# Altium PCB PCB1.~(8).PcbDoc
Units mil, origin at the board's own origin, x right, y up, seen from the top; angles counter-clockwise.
Board outline 2756 x 2756 mil, 4 copper layers (Top Layer, Internal Plane 1, Internal Plane 2, Bottom Layer), stack 18.2 mil thick; 17 components, 14 nets, 62 pads, 0 vias.
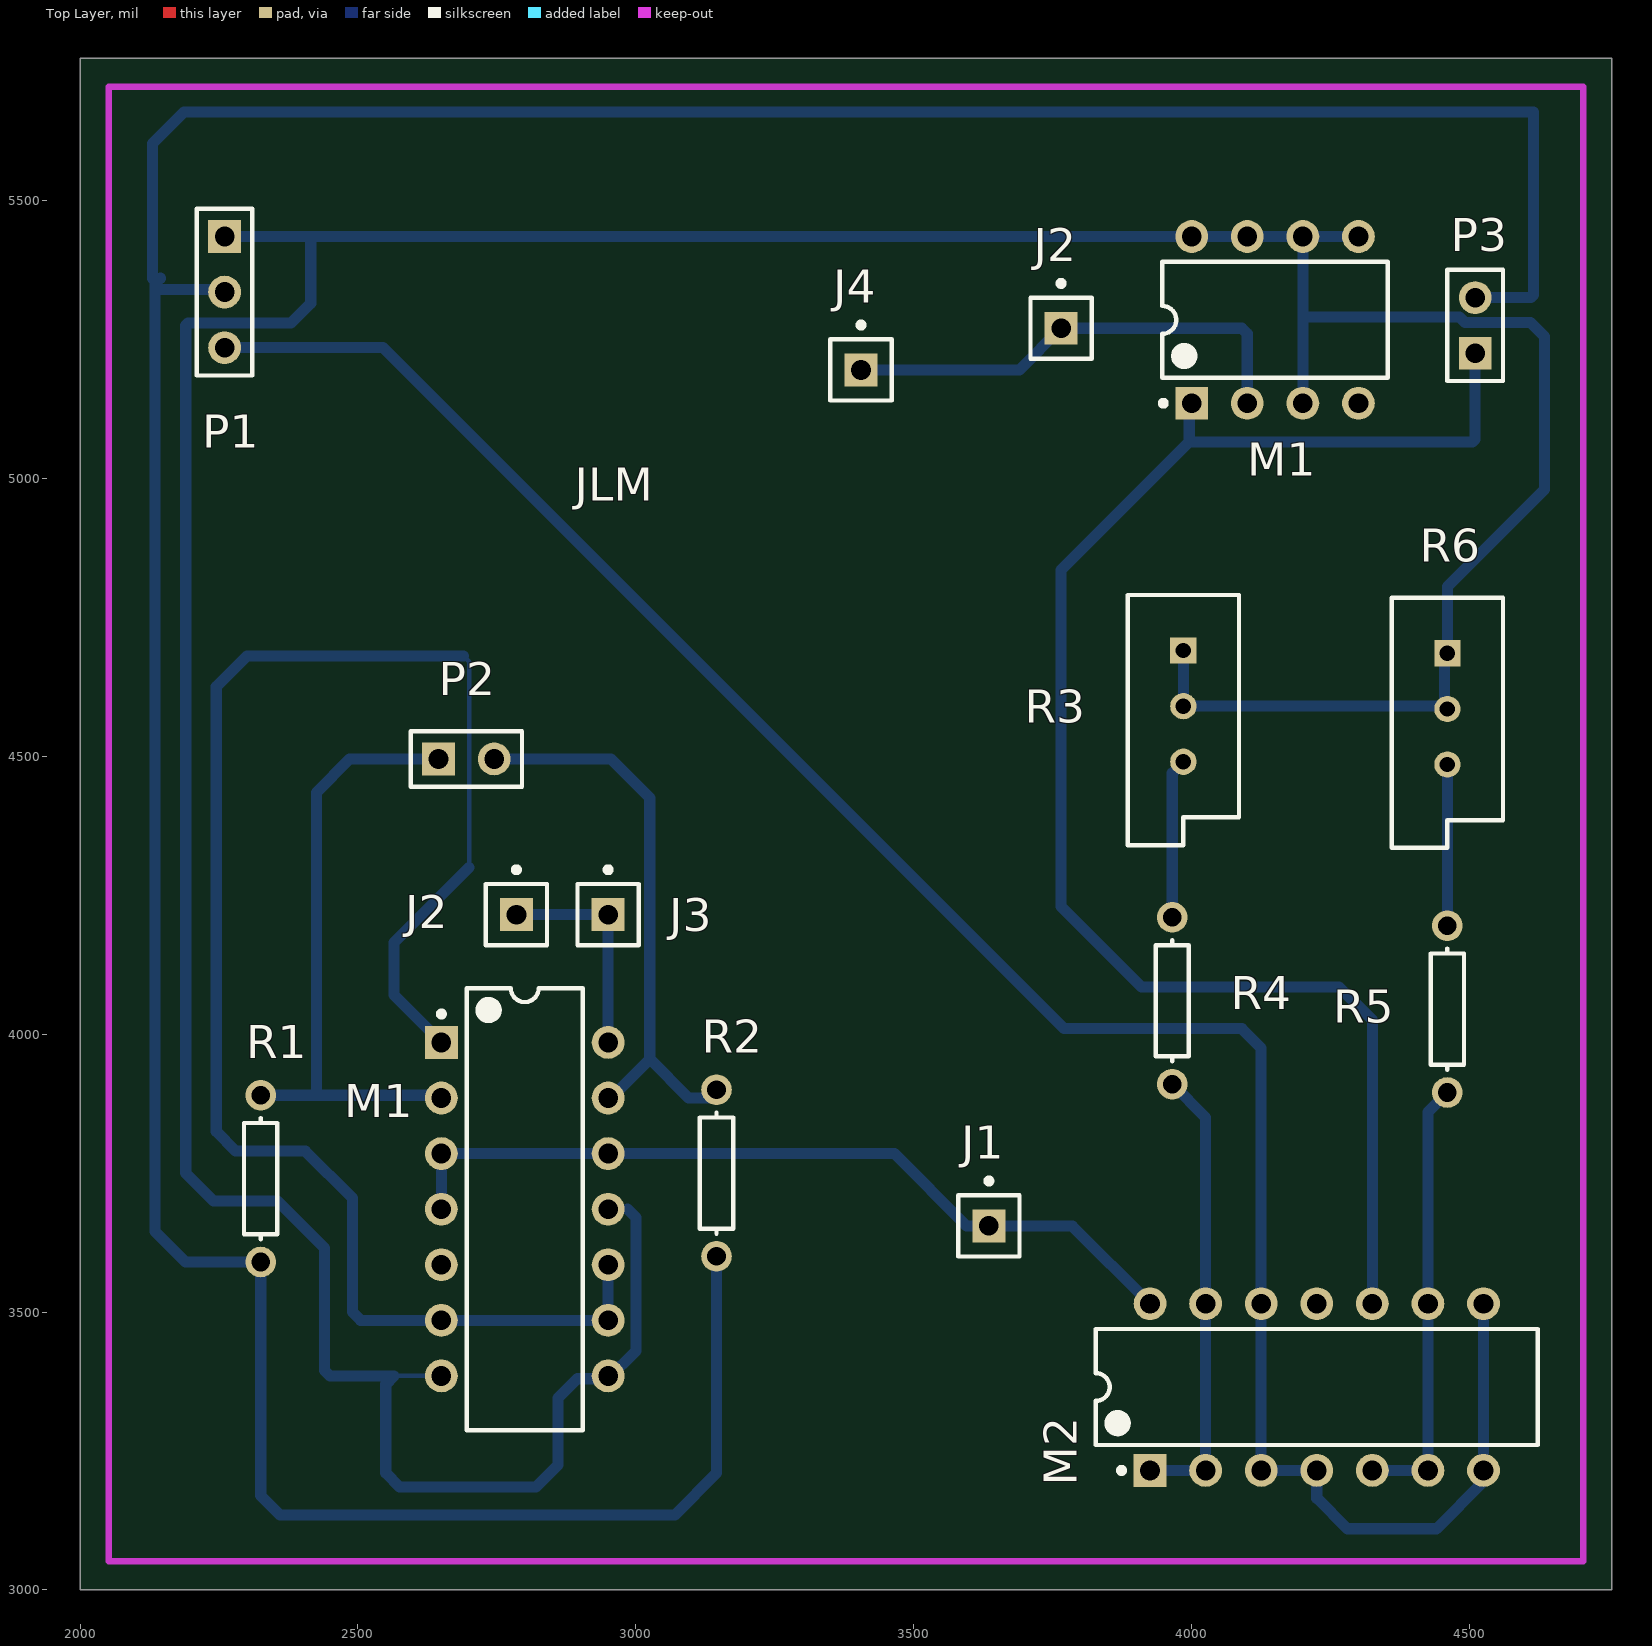
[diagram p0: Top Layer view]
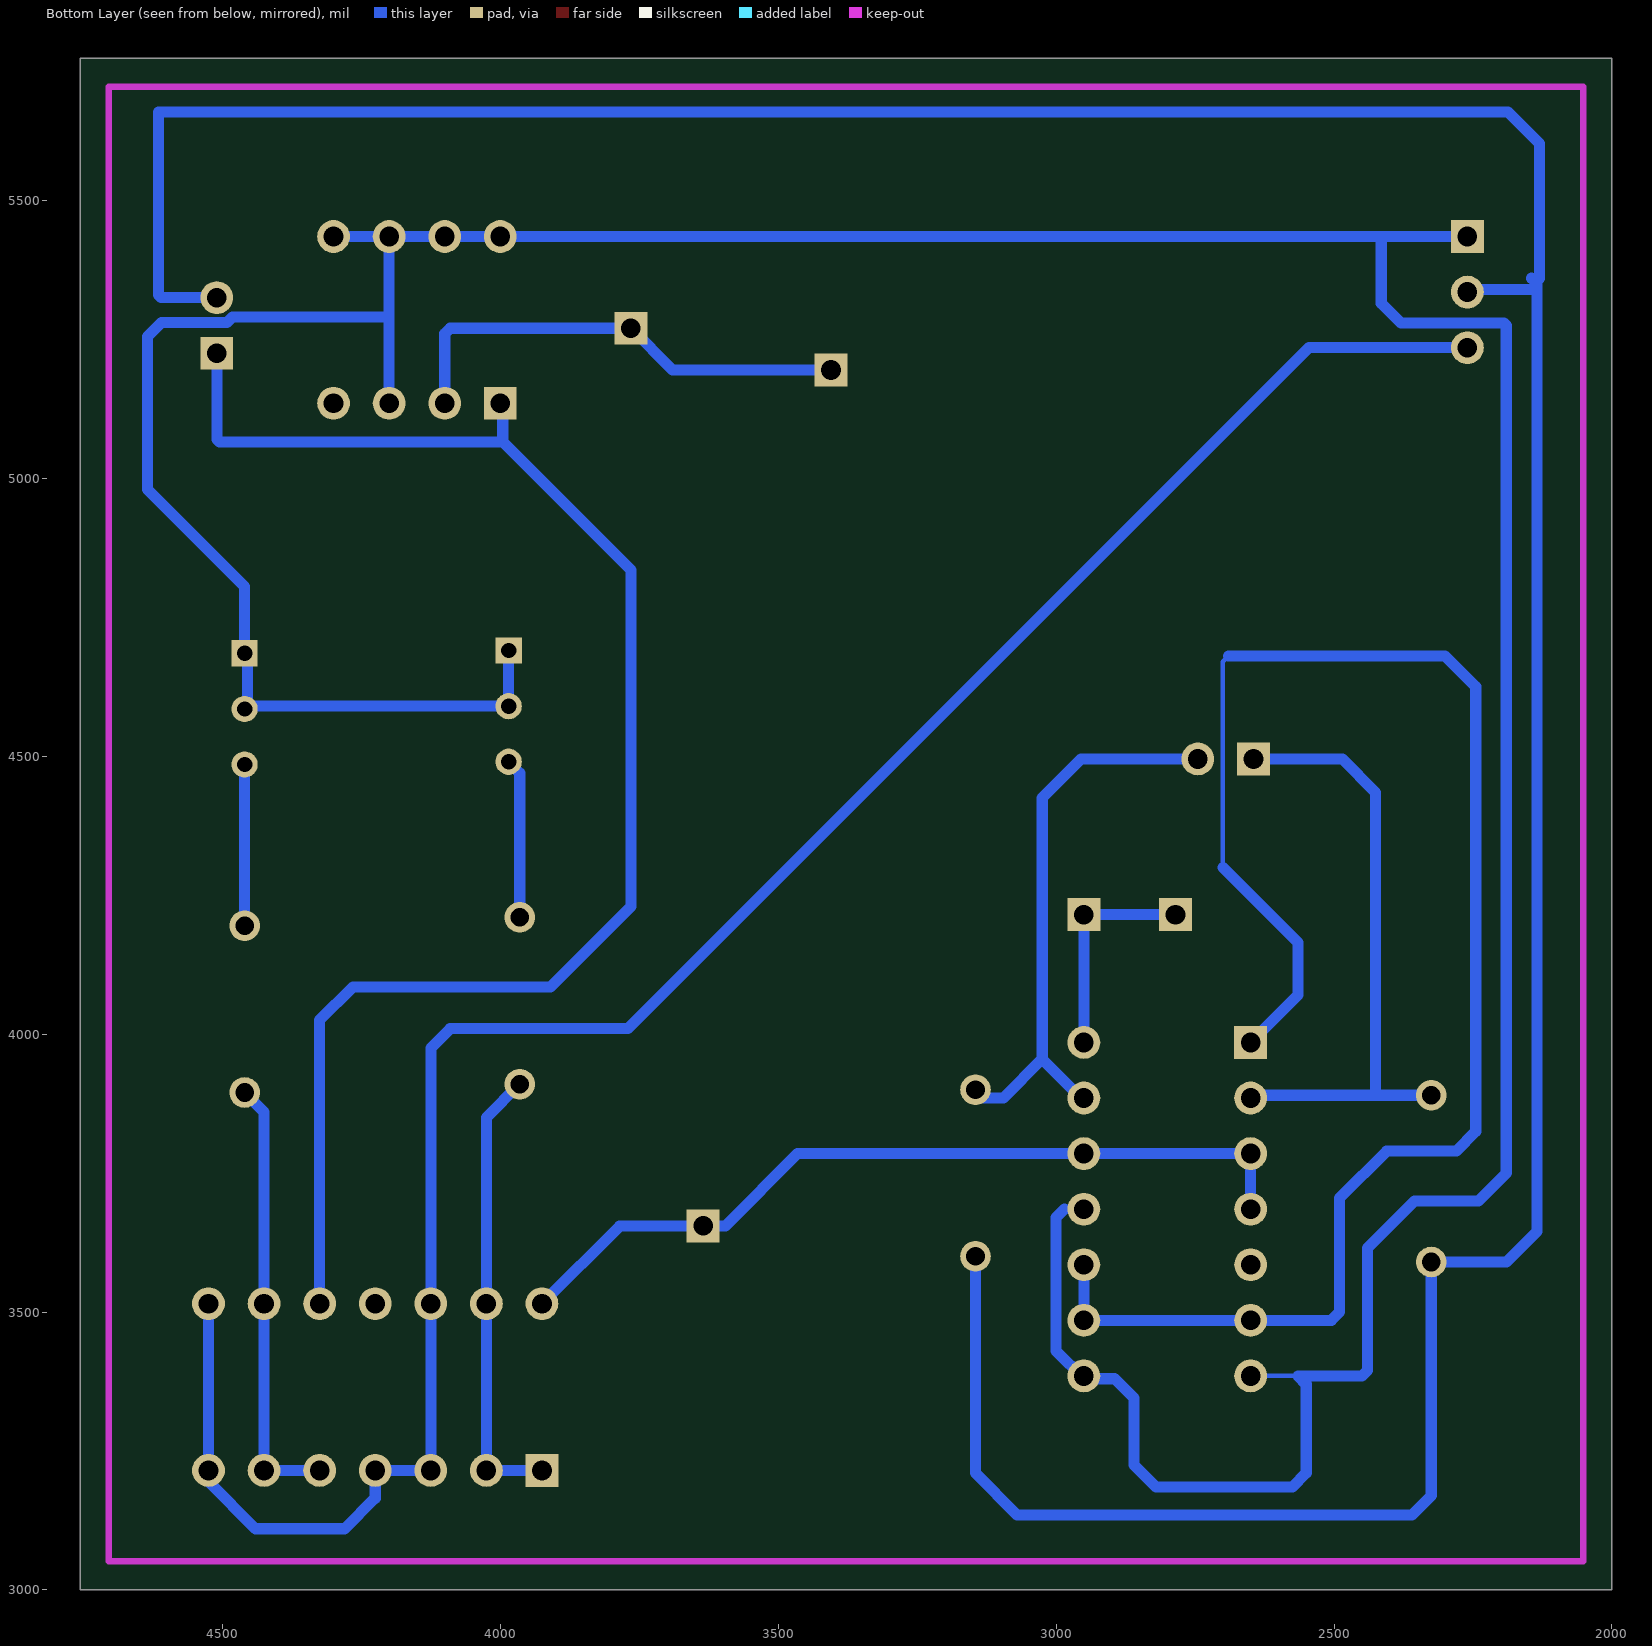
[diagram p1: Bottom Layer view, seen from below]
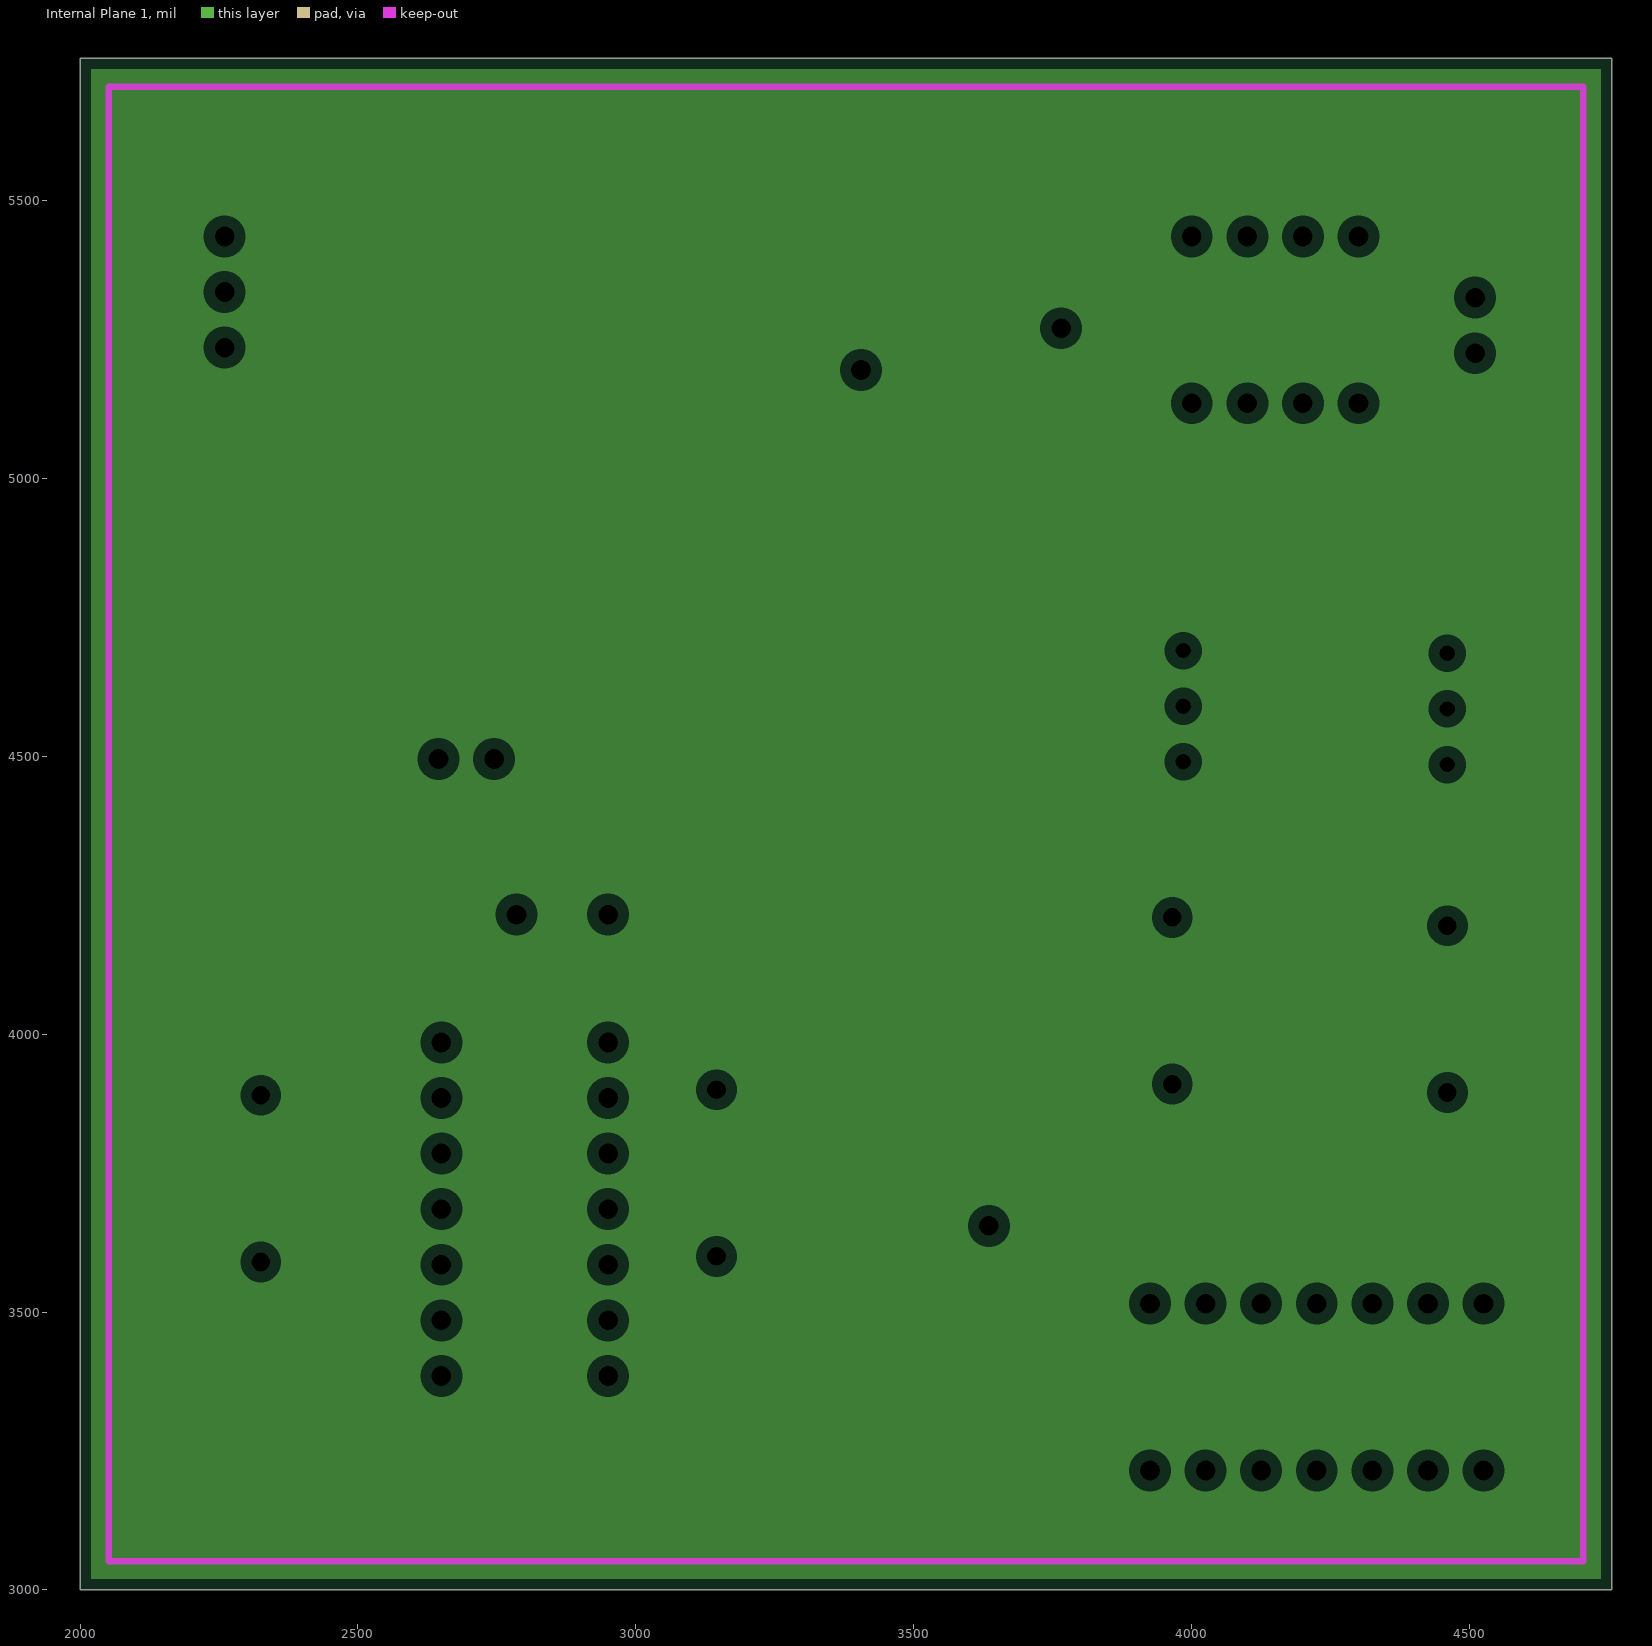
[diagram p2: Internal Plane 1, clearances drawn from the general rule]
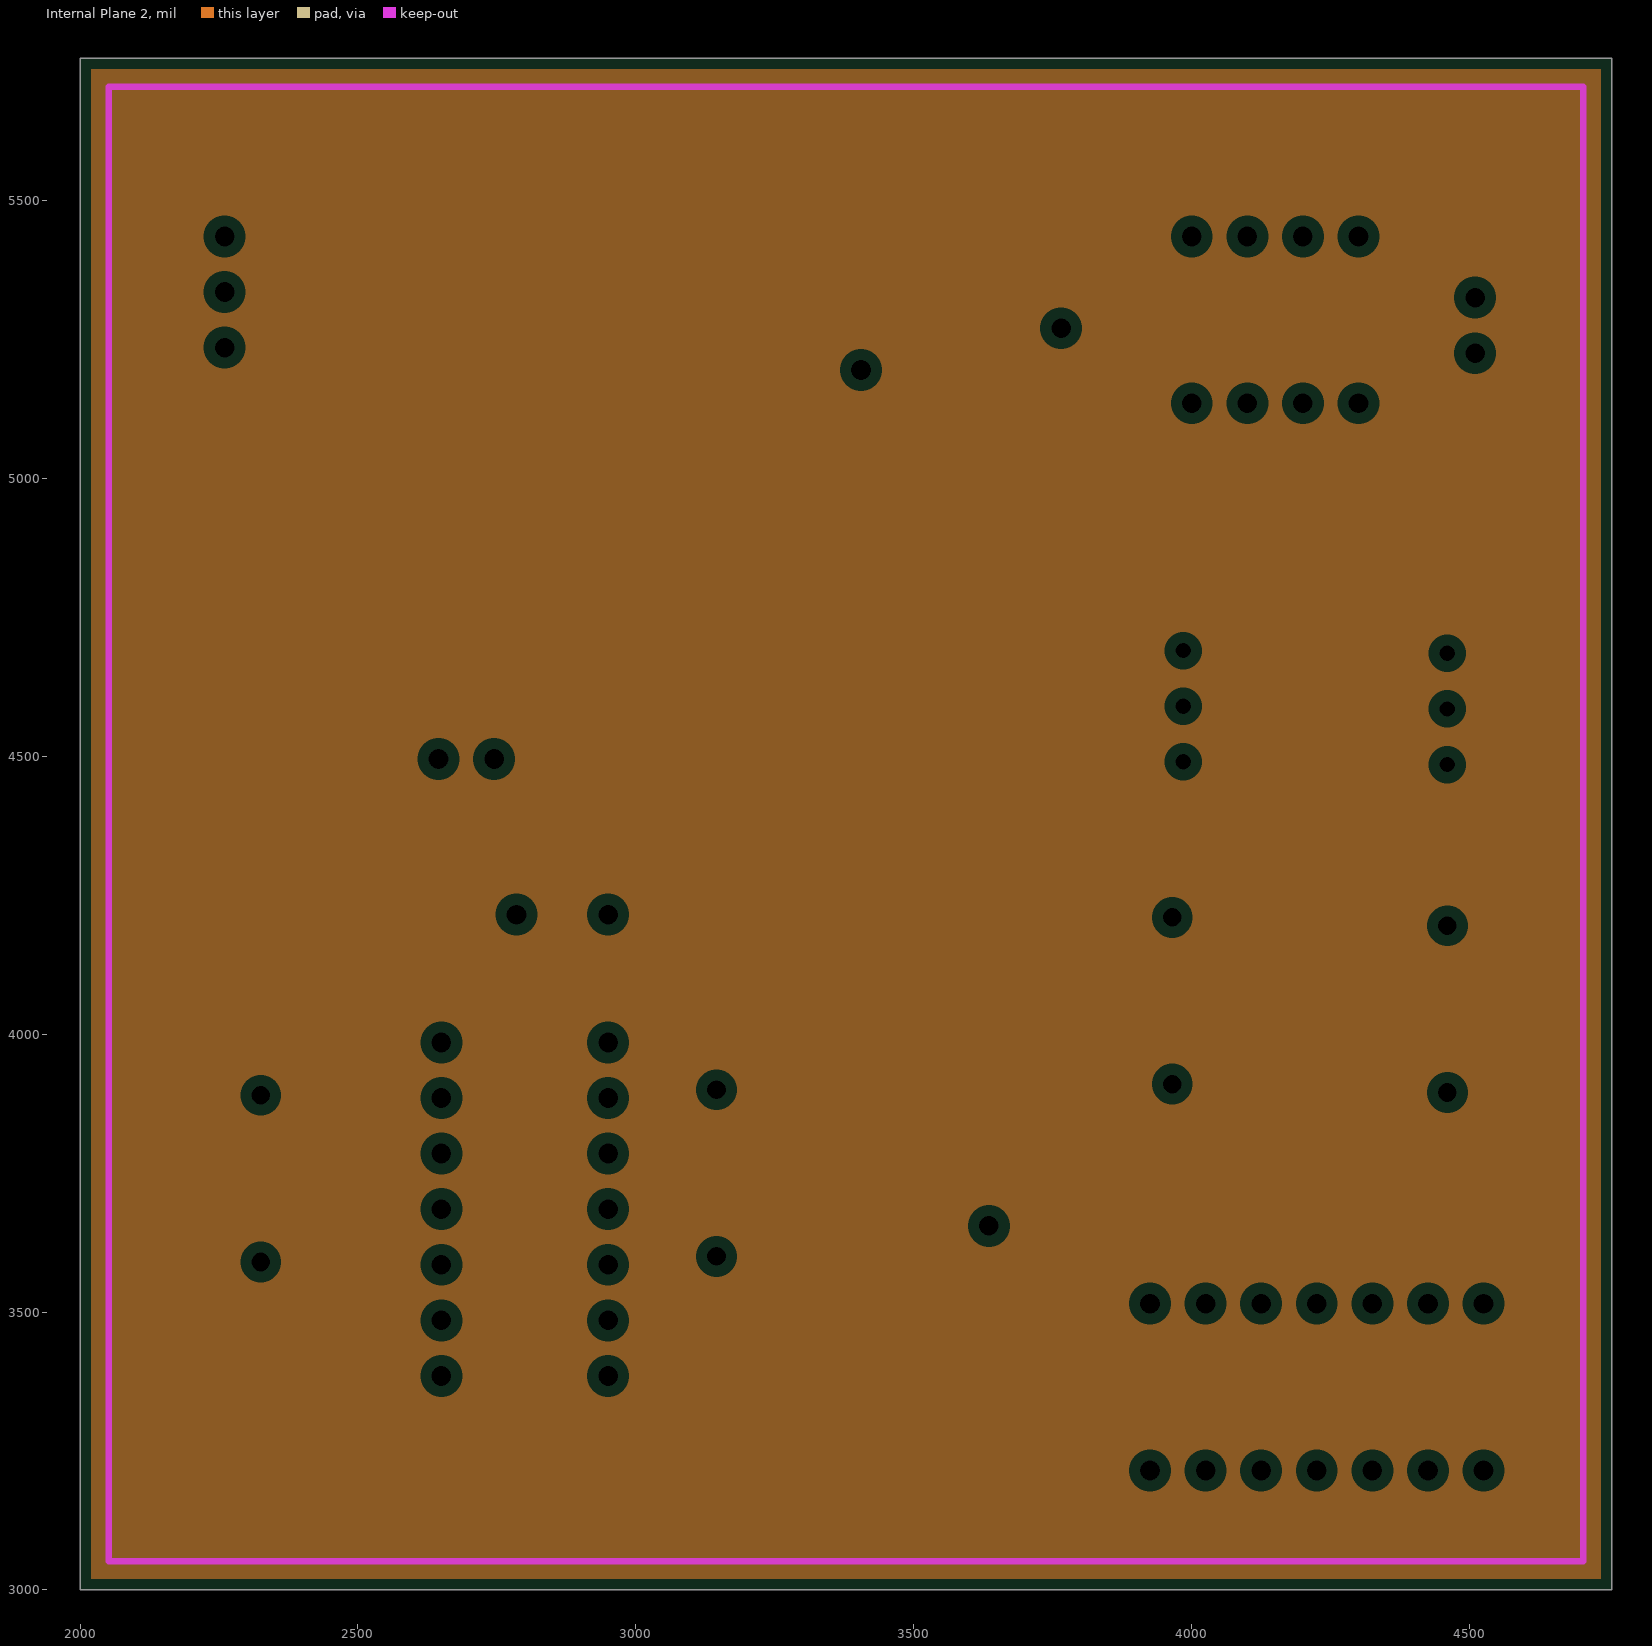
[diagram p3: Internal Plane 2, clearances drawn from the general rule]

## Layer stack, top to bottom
Top Solder: solder mask 0.4, Solder Resist, Dk 3.5
Top Layer: signal copper 1.4
Internal Plane 1: plane copper 1.4
Internal Plane 2: plane copper 1.4
Dielectric 1: dielectric 12.6, FR-4, Dk 4.8
Bottom Layer: signal copper 1.4
Bottom Solder: solder mask 0.4, Solder Resist, Dk 3.5

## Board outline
2000,3000 4756,3000 4756,5756 2000,5756

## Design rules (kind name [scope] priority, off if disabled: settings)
Clearance Clearance_2 [InNet('NetM2_1')] p1: gap=10
Clearance Clearance_1 [InNet('+5')] p2: gap=5
Clearance [All] p3: gap=30
PlaneClearance [All] p1: clearance=20
PlaneConnect [All] p1: planeconnectstyle=Relief reliefexpansion=20 reliefentries=4 reliefconductorwidth=10 reliefairgap=10
PolygonConnect [All] p1: connectstyle=Relief reliefconductorwidth=10 reliefentries=4 polygonreliefangle="90 Angle" airgapwidth=10
RoutingVias [All] p1: holewidth=32 width=62 viastyle="Through Hole" minholewidth=28 minwidth=50 maxholewidth=28 maxwidth=50
SolderMaskExpansion [All] p1: expansion=4
Width Width_1 [InNet('NetJ1_1')] p1: maxlimit=20 minlimit=5 preferedwidth=10 toplayer_minwidth=8 toplayer_maxwidth=10 minimp=50.000000 maximp=50.000000 favimp=50.000000
Width [All] p2: maxlimit=20 minlimit=8 preferedwidth=20 toplayer_minwidth=20 minimp=50.000000 maximp=50.000000 favimp=50.000000
28 further rules are at their usual default settings.

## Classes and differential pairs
component class Sheet1: J1 J2 M1 M2 P1 P2 P4 R1 R2 R3 R4 R5 R6

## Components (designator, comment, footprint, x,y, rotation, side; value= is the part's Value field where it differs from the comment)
J1 "Socket" PIN1 3635,3655 r0 top (schematic designator J2)
J2 "Socket" PIN1 3765,5270 r0 top (schematic designator J1)
J2 "Socket" PIN1 2785,4215 r0 top (schematic designator J?)
J3 "Socket" PIN1 2950,4215 r0 top (schematic designator J?)
J4 "Socket" PIN1 3405,5195 r0 top (schematic designator J?)
M1 "ALD1117" DIP-8 4150,5285 r90 top
M1 "ALD1105" DIP-14 2800,3685 r0 top (schematic designator M2)
M2 "ALD1106" DIP-14 4225,3365 r90 top (schematic designator M3)
P1 "Header 3" HDR1X3 2260,5435 r270 top
P2 "Header 2" HDR1X2 2645,4495 r0 top (schematic designator P4)
P3 "Header 2" HDR1X2 4510,5225 r90 top (schematic designator P2)
R1 "Res1" AXIAL-0.3 2325,3740 r90 top
R2 "Res1" AXIAL-0.3 3145,3750 r90 top
R3 "RPot" VR5 3985,4590 r270 top (schematic designator R4)
R4 "Res1" AXIAL-0.3 3965,4060 r90 top (schematic designator R5)
R5 "RPot" VR5 4460,4585 r270 top (schematic designator R3)
R6 "Res1" AXIAL-0.3 4460,4045 r90 top

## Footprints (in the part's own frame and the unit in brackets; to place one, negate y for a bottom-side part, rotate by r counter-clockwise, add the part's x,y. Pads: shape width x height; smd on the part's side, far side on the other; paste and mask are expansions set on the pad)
AXIAL-0.3 [mm] "Axial Device, Thru-Hole; 2 Leads; 0.3 in Pin Spacing"
  round 1.4 hole 0.85: 1(-3.81,0) 2(3.81,0)
  silkscreen extent -2.77,-0.76 2.77,0.76
DIP-8 [mm] "DIP, 8-Pin, Row Spacing 7.62 mm, Pitch 2.54 mm"
  rect 1.5x1.5 hole 0.9: 1(-3.81,3.81)
  round 1.5 hole 0.9: 2(-3.81,1.27) 3(-3.81,-1.27) 4(-3.81,-3.81) 5(3.81,-3.81) 6(3.81,-1.27) 7(3.81,1.27) 8(3.81,3.81)
  silkscreen extent -3.93,-5.15 2.65,5.23, body extent -3.6,-5.15 3.6,5.15, height 5.33
DIP-14 [mm] "DIP, 14-Pin, Row Spacing 7.62 mm, Pitch 2.54 mm"
  rect 1.5x1.5 hole 0.9: 1(-3.81,7.62)
  round 1.5 hole 0.9: 2(-3.81,5.08) 3(-3.81,2.54) 4(-3.81,0) 5(-3.81,-2.54) 6(-3.81,-5.08) 7(-3.81,-7.62) 8(3.81,-7.62) 9(3.81,-5.08) 10(3.81,-2.54) 11(3.81,0) 12(3.81,2.54) 13(3.81,5.08) 14(3.81,7.62)
  silkscreen extent -3.93,-10.1 2.65,10.1, body extent -3.6,-10.1 3.6,10.1, height 5.08
HDR1X2 [mm] "Connector; Header; 2 Position"
  rect 1.5x1.5 hole 0.9: 1(0,0)
  round 1.5 hole 0.9: 2(2.54,0)
  silkscreen extent -1.27,-1.27 3.81,1.27
HDR1X3 [mm] "Connector; Header; 3 Position"
  rect 1.5x1.5 hole 0.9: 1(0,0)
  round 1.5 hole 0.9: 2(2.54,0) 3(5.08,0)
  silkscreen extent -1.27,-1.27 6.35,1.27
PIN1 [mm] "Connector; Plug"
  rect 1.5x1.5 hole 0.9: 1(0,0)
  silkscreen extent -1.4,-1.4 1.4,2.17
VR5 [mm] "Thru-Hole; 3 Leads"
  rect 1.2x1.2 hole 0.7: 1(-2.54,0)
  round 1.2 hole 0.7: 2(0,0) 3(2.54,0)
  silkscreen extent -5.08,-2.54 6.35,2.54

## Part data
M1: "Dual P-channel matched MOSFET array"
M1: "Dual P-channel and dual N-channel matched MOSFET array"
M2: "Quad N-channel matched MOSFET array"
P1: "Header, 3-Pin"
P2 P3: "Header, 2-Pin"
R1 R2 R4 R6: "Resistor"
R3 R5: "Potentiometer"

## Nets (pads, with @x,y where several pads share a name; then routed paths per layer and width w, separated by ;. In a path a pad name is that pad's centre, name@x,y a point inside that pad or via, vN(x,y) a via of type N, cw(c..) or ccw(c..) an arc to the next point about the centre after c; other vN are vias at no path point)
+5: M1.3@4200,5135 M1.5@4300,5435 M1.6@4200,5435 M1.7 M1.8 M1.11 P1.1 R3.1 R3.2 R5.1 R5.2 | length 7835.2
  Bottom Layer w8: 2565,3385 M1.7@2650,3385 ; M1.11 2985,3685
  Bottom Layer w20: P1.1 2415,5435 ; 2985,3685 3000,3670 3000,3430 2950,3380 2895,3380 2860,3345 2860,3225 2820,3185 2575,3185 2550,3210 2550,3370 2565,3385 2450,3385 2440,3395 2440,3615 2355,3700 2240,3700 2190,3750 2190,5275 2194.53,5279.53 2379.53,5279.53 2415,5315 2415,5435 ; R3.1 R3.2 4455,4590 4455,4680 R5.1 4460,4805 4635,4980 4635,5255 4609.53,5280.47 4491.56,5280.47 4482.03,5290 4200,5290 ; M1.3@4200,5135 4200,5290 ; M1.5@4300,5435 M1.6@4200,5435 ; 2415,5435 4000,5435 4100,5435 M1.6@4200,5435 ; 4200,5290 M1.6@4200,5435
-5: M2.3 M2.4 M2.7 M2.8 M2.12 P1.3 | length 3974.9
  Bottom Layer w20: P1.3 2545,5235 3770,4010 4090,4010 4125,3975 M2.12 M2.3 M2.4 4225,3165 4280,3110 4440,3110 4525,3195 M2.7 M2.8
GND: P1.2 P3.2 R1.1 R2.1 | length 6911.2
  Bottom Layer w20: 2130,5360 2130,5602.09 2186.82,5658.91 4615,5658.91 4615,5330 4610,5325 P3.2 ; 2145,5360 2135,5350 2135,5340 ; P1.2 2255,5340 2135,5340 ; R1.1@2325,3580 2325,3170 2360,3135 3070,3135 3145,3210 R2.1 ; R1.1 2190,3590 2135,3645 2135,5340
NetJ1_1: J2.1@3765,5270 J4.1 M1.2@4100,5135 | length 855.2
  Bottom Layer w20: J4.1 3690,5195 3765,5270 4090,5270 4100,5260 M1.2@4100,5135
NetJ2_1: J1.1 M1.3@2650,3785 M1.4@2650,3685 M1.12 M2.14 | length 1486.8
  Bottom Layer w20: M1.4@2650,3685 2650,3785 3465,3785 3595,3655 J1.1 3785,3655 M2.14
NetJ?_1: J2.1@2785,4215 J3.1 M1.14 | length 395
  Bottom Layer w20: J2.1@2785,4215 J3.1 M1.14
NetM1_1: M1.1@4000,5135 M2.10 P3.1 | length 2828.7
  Bottom Layer w20: M1.1@4000,5135 3995.47,5130.47 3995.47,5065.47 ; M2.10 4325,4025 4265,4085 3910,4085 3765,4230 3765,4835 3995.47,5065.47 ; P3.1 4510,5070 4505.47,5065.47 3995.47,5065.47
NetM2_1: M1.1@2650,3985 M1.6@2650,3485 M1.9 M1.10 | length 3124
  Bottom Layer w8: 2690,4680 2700,4670 2700,4300
  Bottom Layer w20: M1.1@2650,3985 2565,4070 2565,4165 2700,4300 ; 2690,4680 2300,4680 2245,4625 2245,3825 2280,3790 2405,3790 2490,3705 2490,3500 2505,3485 M1.9 M1.10
NetM2_2: M1.2@2650,3885 P2.1 R1.2 | length 1121.9
  Bottom Layer w20: R1.2@2335,3890 2420,3890 ; P2.1 2485,4495 2425,4435 2425,3895 2420,3890 ; M1.2@2665,3890 2420,3890
NetM2_13: M1.13 P2.2 R2.2 | length 1038.2
  Bottom Layer w20: P2.2 2955,4495 3025,4425 3025,3955 ; M1.13 2955,3885 3025,3955 ; R2.2 3130,3885 3095,3885 3025,3955
NetM3_1: M2.1 M2.2 M2.13 R4.1 | length 819.9
  Bottom Layer w20: M2.1 M2.2 M2.13 4025,3850 R4.1
NetM3_5: M2.5 M2.6 M2.9 R6.1 | length 794.5
  Bottom Layer w20: M2.5 M2.6 M2.9 4425,3860 R6.1
NetR3_3: R5.3 R6.2 | length 290
  Bottom Layer w20: R6.2 R5.3
NetR4_3: R3.3 R4.2 | length 288.3
  Bottom Layer w20: R4.2 3965,4470 R3.3
pads on no net: M1.4@4300,5135 M1.5@2650,3585 M2.11

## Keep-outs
Keep-Out Layer:
  lines w11.81: 2051.18,3051.18 2051.18,5704.82 4704.82,5704.82 4704.82,3051.18 2051.18,3051.18

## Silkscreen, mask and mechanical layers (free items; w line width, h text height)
Top Overlay:
  text "JLM" at 2890,4960 h60

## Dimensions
2051.18,3051.18 to 2051.18,5704.82 on Mechanical 1
2051.18,3051.18 to 4704.82,3051.18 on Mechanical 1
